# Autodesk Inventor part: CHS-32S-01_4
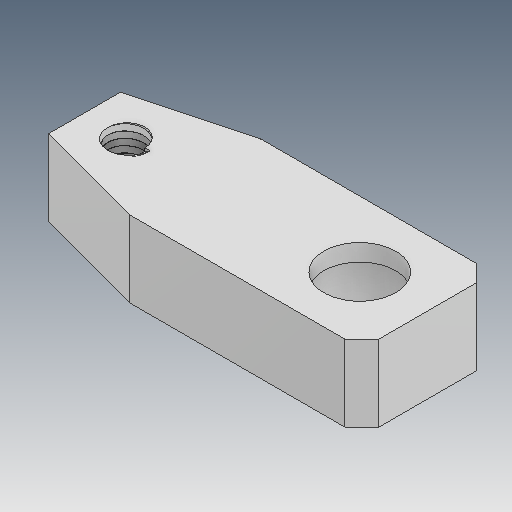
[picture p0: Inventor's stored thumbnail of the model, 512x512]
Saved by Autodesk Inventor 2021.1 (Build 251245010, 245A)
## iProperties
Created: 2021-05
Part Number: CHS-32S-01_4
Material: Ogólny
Document SubType Name: Modeling
Designer: user
Density: 1 g/cm^3
Appearance: Domyślna
Author: user
Revision Number: ÈÎºÎ
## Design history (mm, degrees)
feature "ÊäÈë1"
node "Bryła1"
